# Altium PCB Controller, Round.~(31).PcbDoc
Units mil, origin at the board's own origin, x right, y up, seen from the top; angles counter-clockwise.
Board outline 1800 x 1800 mil, 4 copper layers (Top Layer, Signal 1, Signal 2, Bottom Layer); 49 components, 56 nets, 216 pads, 9 vias.
Unrouted connection lines stored in the file: 62.
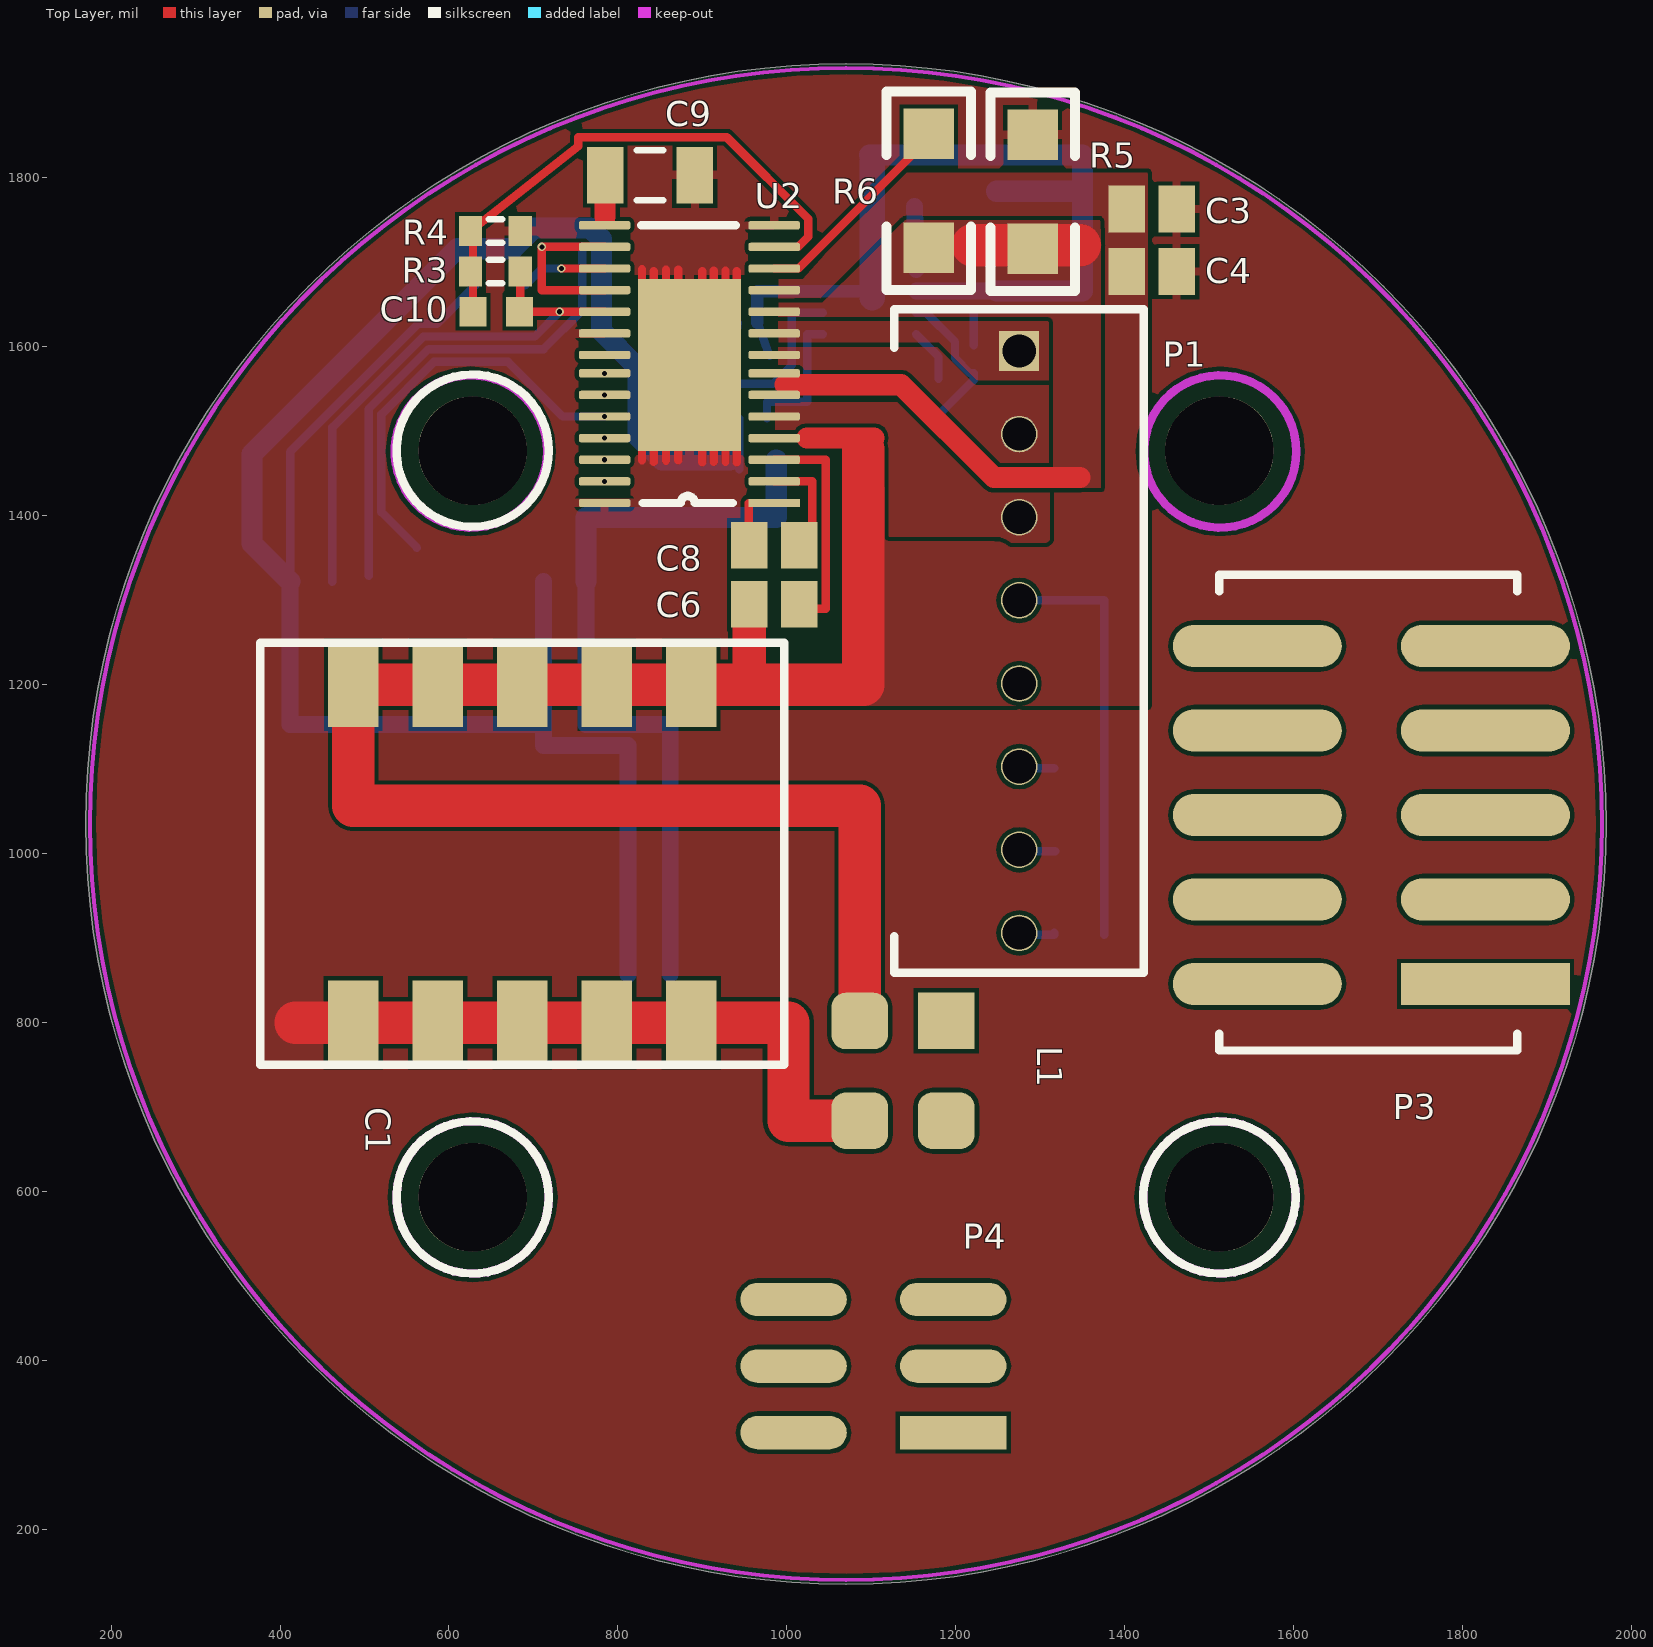
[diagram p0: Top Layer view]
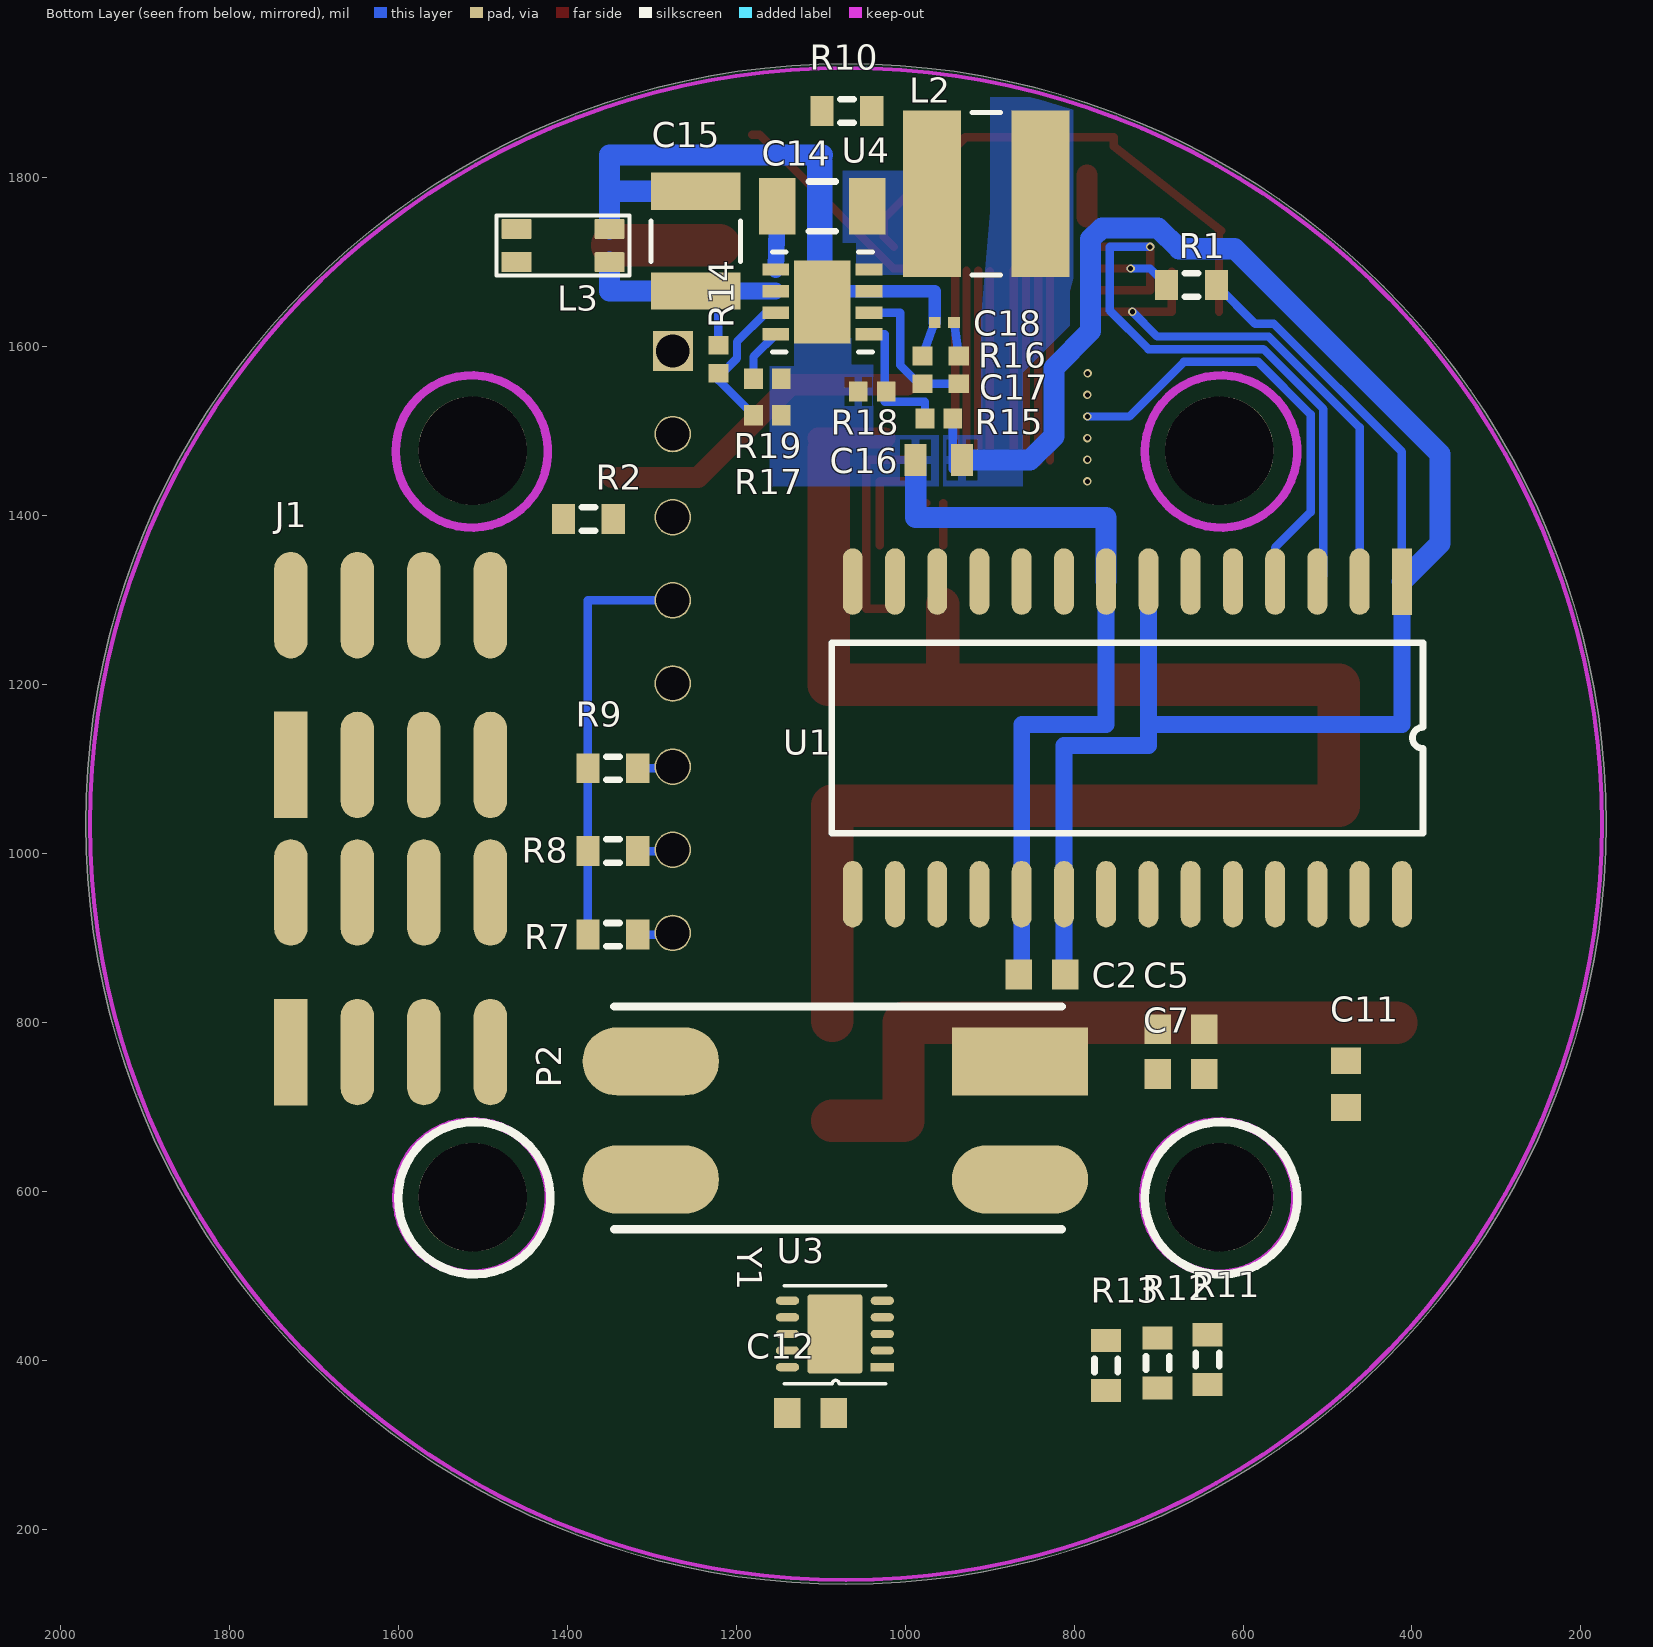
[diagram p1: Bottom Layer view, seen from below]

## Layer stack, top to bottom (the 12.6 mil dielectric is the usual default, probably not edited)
Top Layer: signal copper 1.4
Dielectric: core 12.6, FR-4, Dk 4.8
Signal 1: signal copper 1.4
Dielectric: prepreg 12.6, FR-4, Dk 4.8
Signal 2: signal copper 1.4
Dielectric: core 12.6, FR-4, Dk 4.8
Bottom Layer: signal copper 1.4

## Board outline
1070,135 cw(c1070,1035) 170,1035 cw(c1070,1035) 1070,1935 cw(c1070,1035) 1970,1035 cw(c1070,1035)

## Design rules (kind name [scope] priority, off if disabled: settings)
Clearance [All] p1: gap=5
HoleSize [All] p1: absolutevalues=TRUE maxlimit=130 minlimit=1 maxpercent=80.000 minpercent=20.000
PolygonConnect PolygonConnect_5 [InComponent('L2') vs InNet('VCC')] p1: connectstyle=Direct reliefconductorwidth=10 reliefentries=4 polygonreliefangle="90 Angle"
PolygonConnect PolygonConnect_4 [(InComponent('R19') OR InComponent('R17') OR InComponent('U4')) vs InNet('SGND')] p2: connectstyle=Direct reliefconductorwidth=10 reliefentries=4 polygonreliefangle="90 Angle"
PolygonConnect PolygonConnect_3 [All vs InNet('NetC14_1')] p3: connectstyle=Direct reliefconductorwidth=10 reliefentries=4 polygonreliefangle="90 Angle"
PolygonConnect PolygonConnect_2 [WithinRoom('DontPour1') vs InNet('GND')] p4: connectstyle=NoConnect reliefconductorwidth=10 reliefentries=4 polygonreliefangle="90 Angle"
PolygonConnect PolygonConnect_1 [(InComponent('C1')) vs InNet('GND')] p5: connectstyle=NoConnect reliefconductorwidth=10 reliefentries=4 polygonreliefangle="90 Angle"
PolygonConnect [(InNet('NetP1_1') OR InNet('NetP1_2') OR InNet('NetP1_3') OR InNet('VM') OR InNet('VSENSE')) vs (InNet('NetP1_1') OR InNet('NetP1_2') OR InNet('NetP1_3') OR InNet('VM') OR InNet('VSENSE'))] p6: connectstyle=Direct reliefconductorwidth=10 reliefentries=4 polygonreliefangle="90 Angle"
RoomDefinition Controller [InComponentClass('Controller')] p1 off: confinementstyle=ConfineIn formatcopy=TRUE lockcomponents=FALSE outline -1845,-1985 155,-1985 155,-985 -1845,-985
RoutingVias [All] p1: holewidth=28 width=50 viastyle="Through Hole" minholewidth=6 minwidth=7.5 maxholewidth=28 maxwidth=50
SilkscreenOverComponentPads [All] p1: minsilkscreentomaskgap=10
SolderMaskExpansion [All] p1: expansion=4
Width [InNet('VM')] p1: maxlimit=100 minlimit=20 preferedwidth=40
26 further rules are at their usual default settings.

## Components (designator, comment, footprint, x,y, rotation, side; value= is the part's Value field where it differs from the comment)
C1 "Cap Pol1" CAPSTICK-CS4-5-SMD 486.68,1199.77 r0 top locked
C2 "Cap Semi" 1608[0603] 838,857 r0 bottom
C3 "Cap Semi" C0805 1432,1763 r180 top locked
C4 "Cap Semi" C0805 1432,1689 r180 top locked
C5 "Cap Semi" 1608[0603] 673.56,792 r0 bottom
C6 "Cap Semi" C0805 985,1295 r180 top locked
C7 "Cap Semi" 1608[0603] 673.56,739.11 r0 bottom
C8 "Cap Semi" C0805 985,1365 r180 top locked
C9 "Cap Semi" C1206 838,1803 r180 top locked
C10 "Cap Semi" 1608[0603] 656,1641.38 r180 top locked
C11 "Cap Semi" 1608[0603] 478,727 r270 bottom
C12 "Cap Semi" 1608[0603] 1112,338 r180 bottom
C14 "C1005X7R1E103K" C1206 1098,1766 r0 bottom
C15 "C3225X7R2A225K230AB" 1210 1248,1725 r90 bottom
C16 "C1608X5R0J106M" 0603 960,1466 r0 bottom
C17 "C0402C330J5GAC" 0402 979.5,1572.5 r90 bottom
C18 "GRM033R61A472KA01D" 0201 953.5,1628.5 r0 bottom
J1 "M80-8280842" M8082808DIL 1491,1294 r270 bottom
L1 "DLW5BTM501SQ2" DLW5A_5B 1086.3,801.85 r0 top locked
L2 "LPS5030-823MLB" LPS5030 904,1781 r0 bottom
L3 "SRF3216-222Y" SRF3216 1460,1700 r90 bottom
P1 "MKS 1658-6-0-808" MKS_1658_A_KF 1275,1595 r270 top locked
P2 "M80-8280842" M8082808DIL 1491,954 r270 bottom
P3 "N2510-6V0C-RB-WD" N2510_SMD 1826.98,845.64 r180 top locked
P4 "M80-8280642" M8082806DIL 1008,472 r0 top locked
R1 "Res3" J1-0603 661,1673 r0 bottom
R2 "Res3" J1-0603 1375,1396 r180 bottom
R3 "Res3" J1-0603 655,1689 r0 top locked
R4 "Res3" J1-0603 655,1737 r180 top locked
R5 "Res3" 1206 1291,1851 r270 top locked
R6 "Res3" 1206 1168,1717 r90 top locked
R7 "Res3" J1-0603 1346,904 r0 bottom
R8 "Res3" J1-0603 1346,1003 r0 bottom
R9 "Res3" J1-0603 1346,1101 r0 bottom
R10 "Res3" J1-0603 1069,1879 r0 bottom
R11 "Res3" J1-0603 642,401 r90 bottom
R12 "Res3" J1-0603 701.12,397 r90 bottom
R13 "Res3" J1-0603 762,394 r90 bottom
R14 "CRCW0402665KFKED" 0402 1221,1585 r270 bottom
R15 "CRCW040253K6FKED" 0402 960,1515 r0 bottom
R16 "CRCW040246K4FKED" 0402 936.5,1572.5 r270 bottom
R17 "CRCW040242K2FKED" 0402 1163,1519 r180 bottom
R18 "CRCW040210K0FKED" 0402 1039,1547 r0 bottom
R19 "CRCW040280K6FKED" 0402 1163,1562 r180 bottom
U1 "PIC_SERVO_SC" SOP28 412,1322 r270 bottom
U2 "DRV8313" HTSSOP28 985,1415 r180 top locked
U3 "LTC2864xDD" DD10 1027,392 r0 bottom
U4 "TPS54061DRBR" S-PVSON-N8 1098,1653 r180 bottom
Y1 "MA-506 10.0000M-C0" MA506 864,754 r270 bottom

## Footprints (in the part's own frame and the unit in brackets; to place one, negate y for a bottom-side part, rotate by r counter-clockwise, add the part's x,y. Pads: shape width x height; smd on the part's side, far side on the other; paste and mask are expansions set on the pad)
0201 [mil]
  rect 14x13 smd: 1(-11.5,0) 2(11.5,0)
0402 [mil]
  rect 22x24 smd: 1(-16.5,0) 2(16.5,0)
0603 [mil]
  rect 26x38 smd: 1(-27.5,0) 2(27.5,0)
1206 [mil]
  rect 60x60 smd: 1(0,0) 2(135,0)
  silkscreen extent -50,-50 185,50
1210 [mil]
  rect 44x106 smd: 1(-59,0) 2(59,0)
  silkscreen extent -24,-53 24,53
1608[0603] [mm] "Chip Capacitor, Body 1.6x0.8mm, IPC High Density"
  rect 0.8x0.9 smd: 1(-0.7,0) 2(0.7,0)
  body extent -0.87,-0.48 0.87,0.48, height 1.3
C0805 [mm] "Chip Capacitor, Body 2.0x1.3mm, IPC High Density"
  rect 1.1x1.4 smd: 1(-0.75,0) 2(0.75,0)
  body extent -1.1,-0.72 1.1,0.72, height 1.4
C1206 [mm] "Chip Capacitor, Body 3.2x1.6mm, IPC High Density"
  rect 1.1x1.7 smd: 1(-1.35,0) 2(1.35,0)
  silkscreen extent -0.4,-0.75 0.4,0.75, body extent -1.7,-0.9 1.7,0.9, height 1.3
CAPSTICK-CS4-5-SMD [mil]
  rect 60x100 smd: 1(0,0) 1(100,0) 1(200,0) 1(300,0) 1(400,0) 2(0,-400) 2(100,-400) 2(200,-400) 2(300,-400) 2(400,-400)
  silkscreen extent -110,-450 510,50
DD10 [mm]
  rect 0.7x0.25 smd: 1(0,0)
  oval 0.7x0.25 smd: 2(0,-0.5) 3(0,-1) 4(0,-1.5) 5(0,-2) 6(2.85,-2) 7(2.85,-1.5) 8(2.85,-1) 9(2.85,-0.5) 10(2.85,0)
  rrect10% 1.65x2.38 smd: Pad(1.425,-1)
  silkscreen extent -0.1,-2.45 2.95,0.5
DLW5A_5B [mm]
  rect 1.7x1.7 smd: 1(2.6,0)
  rrect50% 1.7x1.7 smd: 2(0,0) 3(0,-3) 4(2.6,-3)
HTSSOP28 [mm] "HTTSSOP 28 Pin Package, TI"
  rect 1.55x0.25 smd: 1(0,0)
  rrect50% 1.55x0.25 smd: 2(0,-0.65) 3(0,-1.3) 4(0,-1.95) 5(0,-2.6) 6(0,-3.25) 7(0,-3.9) 8(0,-4.45) 9(0,-5.1) 10(0,-5.75) 11(0,-6.4) 12(0,-7.05) 13(0,-7.7) 14(0,-8.35) 15(5.1,-8.35) 16(5.1,-7.7) 17(5.1,-7.05) 18(5.1,-6.4) 19(5.1,-5.75) 20(5.1,-5.1) 21(5.1,-4.45) 22(5.1,-3.9) 23(5.1,-3.25) 24(5.1,-2.6) 25(5.1,-1.95) 26(5.1,-1.3) 27(5.1,-0.65) 28(5.1,0)
  rect 3.1x5.18 smd: Pad(2.55,-4.15)
  silkscreen extent 1.15,-8.35 4,0
J1-0603 [mm] "Chip Resistor, Body 1.6x0.8mm, IPC High Density"
  rect 0.7x0.9 smd: 1(-0.75,0) 2(0.75,0)
  silkscreen extent -0.2,-0.35 0.2,0.35, body extent -0.85,-0.48 0.85,0.48, height 0.9
LPS5030 [mil]
  rect 68.5x197 smd: 1(-64.25,0) 2(64.25,0)
  silkscreen extent -17,-96 17,96
M8082806DIL [mm] "Harwin 2x3"
  rect 3.2x1 smd: 1(4.8,-4)
  oval 3.2x1 smd: 2(0,-4) 3(4.8,-2) 4(0,-2) 5(4.8,0) 6(0,0)
M8082808DIL [mm] "Harwin M80-82808 SMT DIL Male Connector"
  rect 3.2x1 smd: 1(4.8,-6)
  oval 3.2x1 smd: 2(0,-6) 3(4.8,-4) 4(0,-4) 5(4.8,-2) 6(0,-2) 7(4.8,0) 8(0,0)
MA506 [mm]
  rect 2.05x4.1 smd: 1(0,0)
  oval 2.05x4.1 smd: 2(0,-11.1) 3(3.55,-11.1) 4(3.55,0)
  round 0.9 on Bottom Overlay: ""(-0.2,3.15)
  silkscreen extent -1.65,-12.2 5.05,1.26
MKS_1658_A_KF [mm] "Stocko MKS-1658 Shrouded Header Connector"
  rect 1.2x1.2 / inner round 1.2 / far side rect 1.2x1.2 hole 1: 1(0,0)
  round 1.1 hole 1: 2(2.5,0) 3(5,0) 4(7.5,0) 5(10,0) 6(12.5,0) 7(15,0) 8(17.5,0)
  silkscreen extent -1.25,-3.75 18.7,3.75
N2510_SMD [mil]
  rect 200x50 smd: 1(0,0)
  oval 200x50 smd: 2(270.08,0) 3(0,-100) 4(270.08,-100) 5(0,-200) 6(270.08,-200) 7(0,-300) 8(270.08,-300) 9(0,-400) 10(270.08,-400)
  silkscreen extent -37,-484 315,79
S-PVSON-N8 [mm]
  rect 0.805x0.37 smd: 1(-1.402,0.975) 2(-1.402,0.325) 3(-1.402,-0.325) 4(-1.402,-0.975) 5(1.402,-0.975) 6(1.402,-0.325) 7(1.402,0.325) 8(1.402,0.975)
  rect 1.702x2.5 smd paste-1.237: 9(0,0)
  silkscreen extent -1.5,-1.5 1.5,1.5
SOP28 [mm]
  rect 2x0.6 smd: 1(0,0)
  oval 2x0.6 smd: 2(0,-1.27) 3(0,-2.54) 4(0,-3.81) 5(0,-5.08) 6(0,-6.35) 7(0,-7.62) 8(0,-8.89) 9(0,-10.16) 10(0,-11.43) 11(0,-12.7) 12(0,-13.97) 13(0,-15.24) 14(0,-16.51) 15(9.4,-16.51) 16(9.4,-15.24) 17(9.4,-13.97) 18(9.4,-12.7) 19(9.4,-11.43) 20(9.4,-10.16) 21(9.4,-8.89) 22(9.4,-7.62) 23(9.4,-6.35) 24(9.4,-5.08) 25(9.4,-3.81) 26(9.4,-2.54) 27(9.4,-1.27) 28(9.4,0)
  silkscreen extent 1.83,-17.14 7.56,0.63
SRF3216 [mm]
  rect 0.6x0.9 smd: 1(0,0)
  rrect10% 0.6x0.9 smd: 2(0,-2.8) 3(1,-2.8) 4(1,0)
  silkscreen extent -0.4,-3.4 1.4,0.6

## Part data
C1: "Polarized Capacitor (Radial)"
C2 C3 C4 C5 C6 C7 C8 C9 C10 C11 C12: "Capacitor (Semiconductor SIM Model)"
C15: "C3225X7R2A225K23"
C18: "GRM033R61A472KA0"
J1 P2: library part "Header 8", "Header, 8-Pin"
L1 L3: library part "COMMON MODE CHOKE"
P1: library part "Header 8"
P3: library part "Header 5X2", "Header, 5-Pin, Dual row"
P4: library part "Header 6", "Header, 6-Pin"
R1 R2 R3 R4 R5 R6 R7 R8 R9 R10 R11 R12 R13: "Resistor"
U4: "Imported"
Y1: library part MA-406/MA-505/MA-506

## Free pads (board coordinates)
  round 128.5 hole 128.5: ""(628,593) ""(628,1477) ""(1512,593) ""(1512,1477)

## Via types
v1: diameter 10, hole 6, Top Layer to Bottom Layer, 9 vias

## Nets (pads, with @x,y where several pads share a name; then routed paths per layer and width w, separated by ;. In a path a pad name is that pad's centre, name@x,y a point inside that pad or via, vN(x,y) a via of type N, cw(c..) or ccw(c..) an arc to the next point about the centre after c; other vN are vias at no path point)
\ENC_A: P3.5
\ENC_B: P3.7
\ENC_INDEX: P3.9
\FAULT: R11.2 U1.3 U2.16 U2.18 | length 821.1
  Top Layer w10: U2.18 710,1666.97 v1(710,1718.15) U2.16
  Bottom Layer w10: U1.3@504.94,1329.06 504.94,1526.14 575.86,1597.06 712.06,1597.06 757.85,1642.85 757.85,1718.15 v1(710,1718.15)
ADDR_IN: P2.7 U1.28
ADDR_OUT: J1.7 U1.13
CUR_SENSE: C10.1 R3.2 U1.2 U2.19 | length 655.5
  Top Layer w10: R3.2 684.53,1641.38 v1(731,1641.38) U2.19
  Bottom Layer w10: U1.2 462,1504.41 569.64,1612.06 701.68,1612.06 v1(731,1641.38)
ENC_A: P3.6 U1.5
ENC_B: P3.8 U1.6
ENC_INDEX: P3.10 R2.1
GND: C1.2 C3.1 C4.1 C9.1 L1.3 R4.1 R5.1 R10.1 U2.14 U2.20 U2.28 U2.Pad | length 2591.7
  Top Layer w10: 828.5,1465.84 828.5,1691.81 ; 842.22,1463.54 842.22,1689.51 ; 856.94,1465.15 856.94,1691.12 ; 871.27,1465.38 871.27,1691.35 ; 899.94,1463.46 899.94,1689.44 ; 913.66,1464 913.66,1689.97 ; 927.38,1463.85 927.38,1689.82 ; 940.65,1463.23 940.65,1689.21
  Top Layer w50: 418.41,799.77 486.68,799.77 586.68,799.77 686.68,799.77 786.68,799.77 886.68,799.77 1001.81,799.77 1001.81,683.74 L1.3
HALL1: P1.8 R7.1 U1.25 | length 45.5
  Bottom Layer w10: P1.8 1275,905 1275,904 R7.1 R7.1@1316.47,906.02
HALL2: P1.7 R8.1 U1.26 | length 43.1
  Bottom Layer w10: P1.7 1276.45,1003 R8.1@1317.47,1003
HALL3: P1.6 R9.1 U1.27 | length 39.6
  Bottom Layer w10: P1.6@1276.87,1101 R9.1
LIMIT1: P4.2 R13.2 U1.16
LIMIT2: P4.5 R12.2 U1.14
NetC5_2: C5.2 U1.9 Y1.1
NetC6_1: C6.1 U2.3 | length 269
  Top Layer w10: U2.3 1046.18,1466.18 1046.18,1290 C6.1@1014.53,1290
NetC7_2: C7.2 U1.10 Y1.4
NetC8_1: C8.1 U2.2 | length 120.6
  Top Layer w10: U2.2 1030,1440.59 C8.1@1030,1365
NetC8_2: C8.2 U2.1 | length 55.5
  Top Layer w10: C8.2@955,1365 U2.1@955,1415 ; U2.1@975,1415 U2.1@980.47,1415
NetC9_2: C9.2 U2.15 | length 49.4
  Top Layer w25: 784.85,1753.57 C9.2
NetC10_2: C10.2 R3.1 R4.2 U2.13 | length 619.5
  Top Layer w10: R4.2 753.2,1837.2 753,1848 928.87,1848 1025.51,1751.36 1025.51,1730.3 U2.13@1013.36,1718.15 ; C10.2 R4.2@628.44,1737
NetC14_1: C14.1 L2.2 U4.8
NetC14_2: C14.2 U4.1 | length 74.6
  Bottom Layer w20: C14.2 U4.1
NetC15_1: C15.1 L3.2 R14.1 U4.2 | length 267.8
  Bottom Layer w10: R14.1 1221,1639
  Bottom Layer w20: U4.2 C15.1@1247.8,1665.8
  Bottom Layer w25: C15.1 1349.76,1666 L3.2
NetC17_1: C17.1 R16.2 U4.6 | length 177.4
  Bottom Layer w10: R16.2 C17.1 983.64,1556 1006,1578.36 1006,1640.2 U4.6
NetC18_1: C18.1 R16.1 | length 39.9
  Bottom Layer w10: R16.1 C18.1
NetP1_1: P1.1 U2.9
NetP1_2: P1.2 U2.8
NetP1_3: P1.3 U2.5
NetR1_2: R1.2 U2.17 | length 101.8
  Top Layer w10: v1(733,1692.56) U2.17
  Bottom Layer w10: R1.2 710.09,1692.56 v1(733,1692.56)
NetR2_2: R2.2 U1.15
NetR6_2: R6.2 U2.12 | length 261.6
  Top Layer w10: U2.12 1013.98,1692.56 1172.42,1851 R6.2@1181,1851
NetR14_2: R14.2 R17.1 U4.3 | length 175.7
  Bottom Layer w10: U4.3 1164.89,1640.2 1199,1606.09 1199,1586.36 1216.86,1568.5 R14.2 1221,1560.5 R17.1
NetR15_2: R15.2 R18.1 U4.5 | length 165.9
  Bottom Layer w10: R15.2 976.5,1535 1024,1535 1024,1614.61 U4.5
NetR19_1: R19.1 U4.4 | length 63.5
  Bottom Layer w10: U4.4 1179.5,1588.33 R19.1
NetU1_4: U1.4 U2.24 | length 492
  Bottom Layer w10: 562,1362.16 519.94,1404.22 519.94,1519.93 582.07,1582.06 669.93,1582.06 734.63,1517.36 v1(784.21,1517.36)
NetU1_11: U1.11 U2.22
  other v1: 784.04,1568.44
NetU1_12: U1.12 U3.3
NetU1_17: U1.17 U3.4
NetU1_18: U1.18 U3.1
NetU1_21: U1.21 U2.27
  other v1: 784.21,1440.59
NetU1_22: U1.22 U2.25
  other v1: 784.21,1491.77
NetU1_23: U1.23 U2.23
  other v1: 784.21,1542.95
NetU1_24: U1.24 U2.26
  other v1: 784.21,1466.18
"PWR GND": J1.1 L1.4 L3.4 P2.1
RS422_RX_A: J1.3 P2.3 U3.9
RS422_RX_B: J1.4 P2.4 U3.8
RS422_TX_A: J1.5 P2.5 U3.7
RS422_TX_B: J1.6 P2.6 U3.6
SGND: C2.2 C5.1 C7.1 C11.1 C12.2 C15.2 C16.2 C17.2 C18.2 L3.3 P1.5 P3.3 P4.4 P4.6 R10.2 R17.2 R18.2 R19.2 U1.8 U1.19 U3.5 U3.Pad U4.7 U4.9 | length 1753.2
  Bottom Layer w10: U1.19@863,951.92 U1.19 U1.19@865,951.92 ; C18.2 C17.2
  Bottom Layer w15: C18.2 965,1665.8 U4.7 U4.9@1098,1665.8
  Bottom Layer w20: U1.8 762,1153 862,1153 U1.19 C2.2@862,857
  Bottom Layer w25: U1.8 762,1398 987.5,1398 C16.2 ; 1098,1827 1349.76,1827 1349.76,1784 ; C15.2 1349.76,1784 ; L3.3 1349.76,1784
  Bottom Layer w30: U4.9@1101,1657.8 1101,1819
VCC: C2.1 C11.2 C12.1 C16.1 L2.1 P1.4 P3.2 P4.1 P4.3 R1.1 R7.2 R8.2 R9.2 R11.1 R12.1 R13.1 R15.1 U1.1 U1.7 U1.20 U3.10 | length 3116.1
  Bottom Layer w10: U1.1 412,1475.63 563.43,1627.06 585.53,1627.06 R1.1 ; C16.1@943.5,1455 R15.1 ; P1.4 1375.53,1299.72 R9.2 R8.2 R7.2
  Bottom Layer w20: U1.1 412,1153 712,1153 ; U1.7 712,1153 ; C2.1@812,857 U1.20 812,1128 712,1128 712,1153
  Bottom Layer w25: U1.1 367,1367 367,1473 610,1716 676.03,1716 700.68,1740.65 767.17,1740.65 780.35,1727.47 780.35,1618.65 824,1575 824,1494 852,1466 C16.1
VIN: J1.2 L1.1 L3.1 P2.2
VM: C1.1 C3.2 C4.2 C6.2 L1.2 U2.4 U2.11 | length 2054.2
  Top Layer w25: 1024,1491.77 1103,1491.77
  Top Layer w40: 955.47,1200 C6.2
  Top Layer w50: L1.2 1086.3,1056.68 486.68,1056.68 486.68,1199.77 586.68,1199.77 686.68,1199.77 786.68,1199.77 886.68,1199.77 1090.39,1199.77 1090.39,1478.74
VSENSE: R5.2 R6.1 U2.6 U2.7 U2.10 | length 521.6
  Top Layer w25: 997.92,1555 1135,1555 1245,1445 1347,1445
  Top Layer w50: 1220,1720 1347,1720
pads on no net: J1.8 P2.8 P3.1 P3.4 U2.21 U3.2 Y1. Y1.2 Y1.3

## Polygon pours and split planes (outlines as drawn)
GND on Top Layer "Top Layer-No Net" (solid, pour order 100): 949.38,1690.05 949.38,1685.37 949.38,1690.01 819.88,1690.01 819.99,1690.01 819.99,1685.26 819.99,1685.22 949.38,1685.22
VM on Top Layer "Top Layer-No Net" (solid, pour order 76): 989.93,1652.03 1427,1650 1427,1806 1080,1806 1045,1771 1045,1709 1018.56,1680 990.24,1679.93
VSENSE on Top Layer "Top Layer-No Net" (solid, pour order 72): 989.78,1627 1383,1627 1384,1750 1140,1750 1042,1652 990.24,1652.03
NetP1_1 on Top Layer "Top Layer-No Net" (solid, pour order 60): 989.89,1630 1310,1630 1310,1560 1225,1560 1180,1605 990.24,1605.12
NetP1_2 on Top Layer "Top Layer-No Net" (solid, pour order 64): 989.78,1599.6 1310.61,1599.49 1309.78,1450 1243,1450 1241,1452.14 1129,1571.86 1021,1571 989.93,1570.93
GND on Top Layer "Top Layer-No Net" (solid, remove dead copper, pour order 98): 1070,135 cw(c1070,1035) 170,1035 cw(c1070,1035) 1070,1935 cw(c1070,1035) 1970,1035 cw(c1070,1035)
VM on Top Layer "Top Layer-No Net" (solid, pour order 96): 1089.67,1433 1087.44,1174.94 1427,1174.94 1427,1650.24 1377.15,1650.24 1371.74,1433
VSENSE on Top Layer "Top Layer-No Net" (solid, pour order 78): 1315.41,1627 1371.74,1627 1371.74,1433 1366,1433 1315,1433
NetP1_3 on Top Layer "Top Layer-No Net" (solid, pour order 66): 986,1536 988,1534 1155,1534 1163,1534 1259,1438 1261,1436 1311,1436 1311,1362 1305,1356 1304,1357 1109,1357 1109,1484 1099,1494 1093,1500 986,1500
VCC on Bottom Layer "Top Layer-No Net" (solid, pour order 108): 955,1435 955,1495 910,1495 910,1635 899,1760 899,1895 801,1895 801,1681 805,1665.8 805,1625 861,1569 861,1435
SGND on Bottom Layer "Top Layer-No Net" (solid, pour order 106): 1064,1610 1064,1578.36 1038,1578.36 1038,1495 960,1495 960,1435 1160,1435 1160,1577 1131,1577 1131,1610
NetC14_1 on Bottom Layer "Top Layer-No Net" (solid, pour order 102): 1058,1685 1058,1723 1074,1723 1074,1808 986,1808 986,1685

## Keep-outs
Keep-Out Layer:
  circle w5: c1070,1035 r895
  circle w10: c626,1476 r90.15
  circle w10: c1513,1476 r90.15
  circle w10: c1512,593 r90.15
  circle w10: c628,593 r90.15

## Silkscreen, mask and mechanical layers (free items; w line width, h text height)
Top Overlay:
  circle w10: c628,593 r90.15
  circle w10: c628,1477 r90.15
  circle w10: c1512,593 r90.15
Bottom Overlay:
  circle w10: c626,592 r90.15
  circle w10: c1510,592 r90.15
Mechanical 1:
  circle w5: c1512,1477 r64.25
  circle w5: c1512,593 r64.25
  circle w5: c628,593 r64.25
  circle w5: c628,1477 r64.25
  circle w5: c1070,1035 r900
